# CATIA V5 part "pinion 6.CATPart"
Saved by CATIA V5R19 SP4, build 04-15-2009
Part number: pinion 6
Bounding box of the stored display mesh (mm): x 0 to 22.15, y -24.146 to 24.146, z -23.97 to 23.97
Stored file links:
  G:\EU_thinkMotion\CFAO_2010\MMS_groupe1\MMS_groupe1\A reprendre\OK\rdeneffle\pinion 6.CATPart
  G:\EU_thinkMotion\CFAO_2010\MMS_groupe1\MMS_groupe1\A reprendre\OK\rdeneffle\pinion 2.CATPart
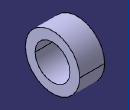
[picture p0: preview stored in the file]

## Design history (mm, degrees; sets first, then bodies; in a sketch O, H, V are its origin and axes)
Parameters
  `rayon interieur.1` = 15.505 mm
  `rayon extérieur.1` = 24.146 mm
Body1 (main body)
Body2
  Sketch1 on yz-plane, origin (0, 0, 0), H (0, 1, 0), V (0, 0, 1)
    circle A1 centre (0, 0) radius 15.505
    circle A2 centre (0, 0) radius 24.146
    radius A2 = 24.146 {= `rayon extérieur.1`}
    radius A1 = 15.505 {= `rayon interieur.1`}
  Pad1: profile Sketch1, direction (1, 0, 0), length 22.15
